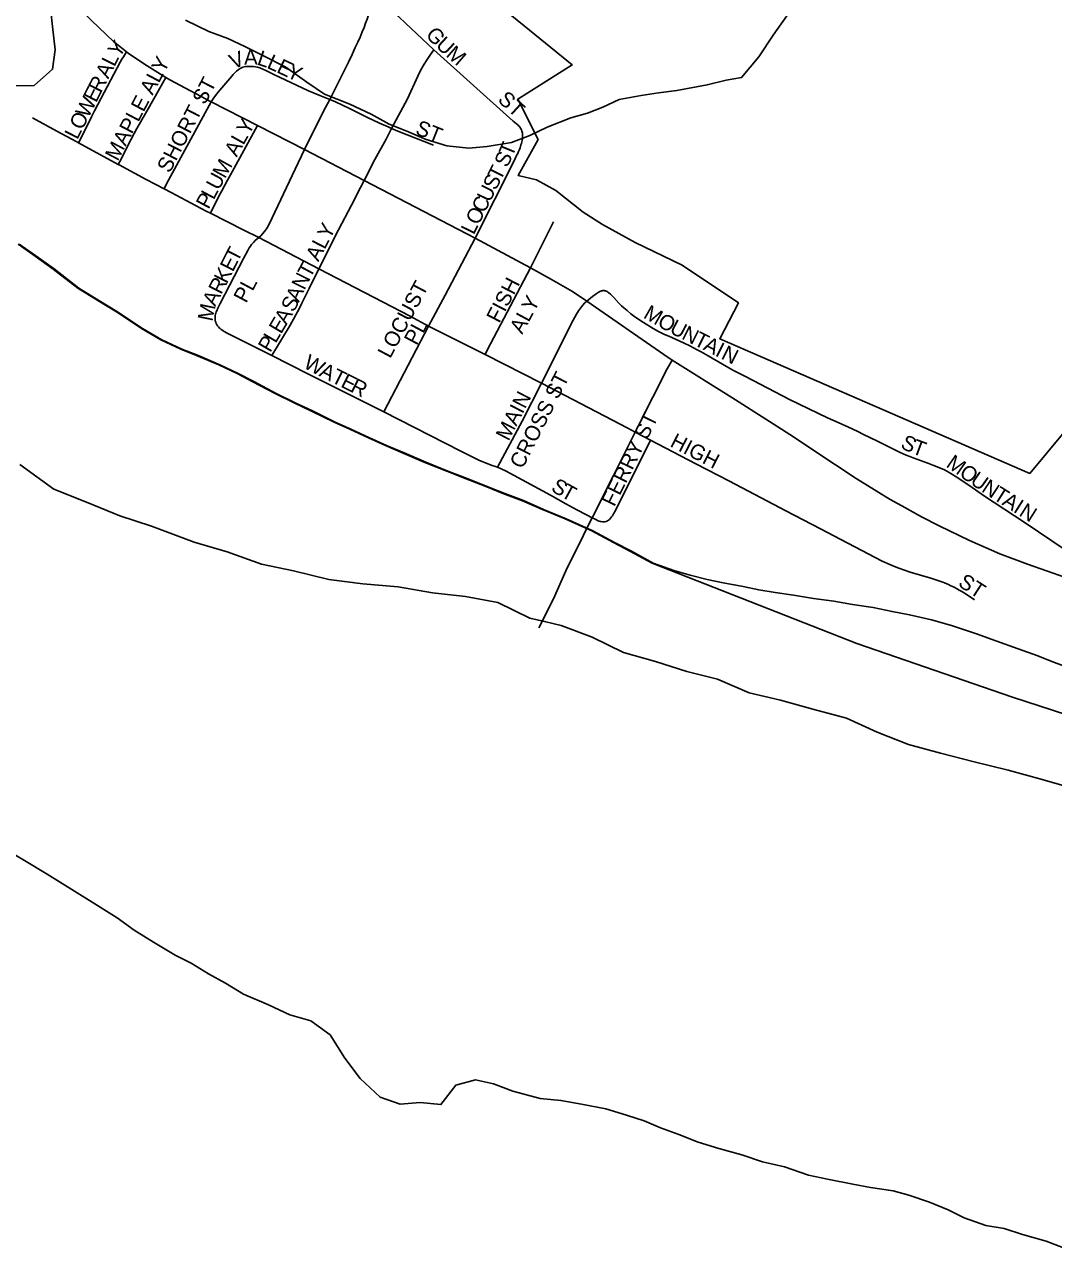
# Model space of a CAD drawing. Extents: x 1451455 to 1749751, y 218250 to 574981.
# Drawn here: x 1607283 to 1610664, y 237680 to 241704 of the extents above; entities that cross this region are included whole.
import ezdxf

# ---------------------------------------------------------------- set-up
doc = ezdxf.new("R2010")
doc.units = 0
for name, color, linetype in [('GM_X_City_Street', 7, 'Continuous'), ('GM_X_City_Street_Text', 7, 'Continuous'), ('GM_X_Corporation', 7, 'Continuous'), ('GM_X_County', 7, 'Continuous'), ('GM_X_Major_River', 7, 'Continuous'), ('GM_X_Minor_River', 7, 'Continuous'), ('GM_X_State_Route', 7, 'Continuous'), ('GM_X_Township', 7, 'Continuous'), ('GM_X_US_Route', 7, 'Continuous')]:
    doc.layers.add(name, color=color, linetype=linetype)

msp = doc.modelspace()

# ---------------------------------------------------------------- linework, layer by layer
at = {"layer": 'GM_X_City_Street'}
for points in [[(1608429.3, 241787.9), (1608449.2, 241777.7), (1608463.9, 241769.2), (1608472.3, 241763.6), (1608479, 241758.7), (1608487.2, 241751.9), (1608515.3, 241727), (1608533.8, 241710.1), (1608628.5, 241621.2)], [(1607460.8, 241315.5), (1607465.7, 241325.6), (1607503.3, 241401.1), (1607513.4, 241420.6), (1607556, 241501.1), (1607597.7, 241580.2), (1607603.4, 241590.2), (1607608.2, 241598.1), (1607611.9, 241603.8), (1607618.9, 241614.4)], [(1608489.5, 241362.4), (1608541.2, 241460.3), (1608575.4, 241534.4), (1608585.8, 241555.6), (1608596.9, 241574.4), (1608606.3, 241589.6), (1608617.5, 241605.8), (1608628.5, 241621.2)], [(1608628.5, 241621.2), (1608889.2, 241387), (1608904.8, 241373.5), (1608907.7, 241370.5), (1608909.4, 241368.6), (1608910.8, 241366.9), (1608912.7, 241364.2), (1608914.4, 241361.6), (1608915.8, 241358.7), (1608917.7, 241354), (1608918.7, 241350.7), (1608919.4, 241347.3), (1608919.8, 241343.6)], [(1607896.5, 241449.8), (1607905.5, 241463), (1607914.5, 241475.1), (1607925.3, 241488), (1607957.9, 241526.6), (1607964.1, 241534), (1607969.1, 241539.6), (1607974.2, 241545.2), (1607980.1, 241551), (1607985.2, 241555.4), (1607991.6, 241559.9), (1607995.9, 241562.1), (1608000.2, 241563.6), (1608004.6, 241564.9), (1608009.6, 241565.9), (1608015.4, 241566.4), (1608021.3, 241566.6), (1608028.4, 241566.4), (1608035.4, 241566), (1608042.4, 241565), (1608048.3, 241563.8), (1608056.1, 241561.5), (1608065.9, 241557.7), (1608076.2, 241552.9), (1608102.4, 241540.4), (1608216.3, 241485.9), (1608253.9, 241470.9), (1608285.9, 241458.1)], [(1607591.5, 241244.4), (1607596.6, 241254.4), (1607632.8, 241325.6), (1607643.5, 241346), (1607652.6, 241362.7), (1607681.1, 241411.8), (1607712.7, 241468), (1607737.5, 241512.2), (1607747.8, 241530.5)], [(1607741.7, 241164.7), (1607750.3, 241180.7), (1607896.5, 241449.8)], [(1608285.9, 241458.1), (1608305.5, 241450.3), (1608350.7, 241428.7), (1608410.2, 241398.9), (1608449.7, 241380.3), (1608478, 241367.5), (1608489.5, 241362.4)], [(1607309.3, 241397.4), (1607389.5, 241353.6)], [(1607893.9, 241084.5), (1607922.2, 241139.9), (1607931.6, 241157.9), (1607950.1, 241192.6), (1607965.6, 241220.5), (1608048.7, 241371.9)], [(1608399.6, 241191.8), (1608434.8, 241260.7), (1608471.1, 241328), (1608489.5, 241362.4)], [(1608489.5, 241362.4), (1608509.7, 241353.9), (1608626.8, 241307.7)], [(1607389.5, 241353.6), (1607453.1, 241319.7), (1607460.8, 241315.5)], [(1607460.8, 241315.5), (1607591.5, 241244.4)], [(1608763.7, 241002.2), (1608891.9, 241256), (1608896.8, 241266.4), (1608900.2, 241273.5), (1608903.6, 241280.9), (1608906.2, 241286.7), (1608909.1, 241293.6), (1608911.3, 241299.5), (1608914.5, 241308.7), (1608915.9, 241313.6), (1608917.2, 241318.6), (1608918.2, 241323.6), (1608918.9, 241327.7), (1608919.6, 241333.4), (1608919.7, 241336.2), (1608919.8, 241340.1), (1608919.8, 241343.6)], [(1608052.7, 241004.5), (1608059.2, 241010.4), (1608065.7, 241017), (1608071.8, 241023.9), (1608078.5, 241032.9), (1608081.9, 241038.1), (1608087.4, 241048.5), (1608172.7, 241229.1), (1608203.2, 241293.5)], [(1607591.5, 241244.4), (1607593.8, 241243.2), (1607683.3, 241195.3), (1607741.7, 241164.7)], [(1607741.7, 241164.7), (1607764.6, 241152.7), (1607880.3, 241091.2), (1607893.9, 241084.5)], [(1608250.5, 240901.9), (1608315.3, 241029.2), (1608357.9, 241110.3), (1608387.7, 241168.4), (1608399.6, 241191.8)], [(1607893.9, 241084.5), (1608004.4, 241028.7), (1608052.7, 241004.5)], [(1608946.2, 240905.2), (1609021.1, 241056.3)], [(1607910.1, 240731.3), (1607909.7, 240735.3), (1607909.5, 240739.7), (1607909.6, 240741.6), (1607909.9, 240746.2), (1607910.2, 240748.3), (1607911, 240752.8), (1607911.7, 240755.6), (1607913.4, 240760.8), (1607914.8, 240764.1), (1607918.8, 240772.6), (1607926.3, 240787.7), (1608002.8, 240935.4), (1608017.1, 240962.3), (1608021.5, 240970.1), (1608025.3, 240975.9), (1608029.3, 240981.2), (1608035.8, 240988.6), (1608041.6, 240994.2), (1608052.7, 241004.5)], [(1608052.7, 241004.5), (1608250.5, 240901.9)], [(1608611, 240713.7), (1608665.3, 240814.8), (1608763.7, 241002.2)], [(1608095.9, 240616.5), (1608155.7, 240716.8), (1608166.8, 240735.8), (1608174.8, 240750.1), (1608180.2, 240760.3), (1608185.2, 240770.3), (1608194.2, 240788.6), (1608218.2, 240837.3), (1608250.5, 240901.9)], [(1608250.5, 240901.9), (1608550.1, 240746.3), (1608611, 240713.7)], [(1608796.5, 240620.1), (1608803.8, 240634), (1608946.2, 240905.2)], [(1608982.3, 240526.1), (1609085.9, 240732.8), (1609096.7, 240752.9), (1609103.5, 240764), (1609116.3, 240781.4), (1609123, 240788.5), (1609130.5, 240795.4)], [(1609130.5, 240795.4), (1609149.3, 240811.1), (1609161.2, 240820), (1609167.7, 240824), (1609173.2, 240826.9), (1609176.9, 240828.4), (1609178.6, 240829), (1609181.2, 240829.6), (1609182.9, 240829.9), (1609185.1, 240830.2), (1609186.1, 240830.2), (1609188.2, 240830), (1609190.2, 240829.8), (1609192.5, 240829.2), (1609194.7, 240828.4), (1609197.6, 240826.8), (1609200.1, 240825.3), (1609202.9, 240823.2), (1609208.7, 240818.1), (1609219.6, 240807.1), (1609235.7, 240789.3), (1609244.7, 240780.4), (1609252.1, 240773.5), (1609263.1, 240764.3), (1609275.7, 240754.2), (1609288.2, 240744.2), (1609316.5, 240724.9), (1609348.3, 240706.1), (1609366, 240696.2), (1609379.1, 240689.4), (1609386, 240686.1), (1609399.7, 240680), (1609409.7, 240675.8), (1609426.4, 240668.4), (1609434.4, 240664.6), (1609450.9, 240657), (1609469, 240648.5), (1609493.7, 240635.8), (1609507, 240628.4), (1609529.1, 240615.3), (1609610.2, 240568.8), (1609652.5, 240547.6), (1609796.8, 240472.8), (1609922, 240412.1), (1609956.8, 240397.1), (1610002.5, 240375.8), (1610020.7, 240366.9), (1610039.3, 240357.4), (1610083.1, 240336.3), (1610134.4, 240311.3), (1610160.1, 240298.6), (1610180.1, 240289.7), (1610191.8, 240284.9), (1610203, 240280.5), (1610250.9, 240263.5)], [(1607910.1, 240731.3), (1607911.4, 240726.4), (1607912.8, 240722.4), (1607914.1, 240719.7), (1607916, 240716.4), (1607917.2, 240714.7), (1607919.5, 240711.7), (1607920.4, 240710.6), (1607924, 240706.9), (1607925.9, 240705.2), (1607929.3, 240702.5), (1607931.1, 240701.2), (1607935.5, 240698.2), (1607939.2, 240695.8), (1607948.6, 240690.6), (1608095.9, 240616.5)], [(1608463.7, 240432.3), (1608543.9, 240585.5), (1608611, 240713.7)], [(1608611, 240713.7), (1608796.5, 240620.1)], [(1608095.9, 240616.5), (1608214.5, 240556.9), (1608463.7, 240432.3)], [(1608796.5, 240620.1), (1608982.3, 240526.1)], [(1608837.2, 240250.5), (1608918.1, 240401.5), (1608982.3, 240526.1)], [(1608982.3, 240526.1), (1609265.3, 240378), (1609289.9, 240365.1), (1609340.1, 240338.7)], [(1608463.7, 240432.3), (1608717.1, 240302.3), (1608778.5, 240272.1), (1608797.8, 240263.8), (1608816.5, 240256.7), (1608837.2, 240250.5)], [(1609194.2, 240071.4), (1609198.8, 240073.3), (1609202.3, 240075.5), (1609205.5, 240078.2), (1609208.8, 240082.1), (1609212.2, 240086.6), (1609214.8, 240090.5), (1609218.8, 240097.2), (1609223.8, 240106.1), (1609266.3, 240192.1), (1609330.9, 240320.5), (1609340.1, 240338.7)], [(1609340.1, 240338.7), (1609488.9, 240261.4), (1609599.7, 240204), (1609784.9, 240106.9), (1609898.8, 240047.5), (1610101.5, 239941.7), (1610126.2, 239930.3), (1610141.5, 239923.9), (1610156, 239918.3), (1610174.1, 239911.9), (1610193.6, 239905.4), (1610260.8, 239885.4), (1610277.6, 239880), (1610290.5, 239875.5), (1610300.1, 239872), (1610305.9, 239869.8), (1610314.1, 239866.4), (1610319, 239864.3), (1610326.9, 239860.8), (1610335.2, 239856.8), (1610345.7, 239851.2), (1610354.4, 239846.5), (1610362.6, 239841.6), (1610376.8, 239832.9), (1610404.2, 239814.6)], [(1608837.2, 240250.5), (1608863.1, 240237.6), (1608932.8, 240201), (1609010.9, 240158.2), (1609062.2, 240129.9), (1609098.5, 240110.2), (1609129.9, 240093.5), (1609148.4, 240084), (1609157.8, 240079.2), (1609168.3, 240074.2), (1609171.7, 240073), (1609175.1, 240071.9), (1609178.4, 240071.1), (1609182, 240070.6), (1609185.9, 240070.4), (1609189.8, 240070.7), (1609194.2, 240071.4)], [(1610250.9, 240263.5), (1610268.1, 240257), (1610292.5, 240247), (1610306, 240240.8), (1610321.6, 240232.4), (1610340.5, 240220.9), (1610385.4, 240190.6), (1610436.9, 240154.9), (1610567.5, 240069.1), (1610706.2, 239976.3)]]:
    msp.add_lwpolyline(points, dxfattribs=at)
at = {"layer": 'GM_X_Corporation'}
for points in [[(1608422.8, 242108.6), (1609082.9, 241571.6), (1608903.8, 241459), (1608970.7, 241325.9), (1608905.6, 241208.1), (1608965.6, 241193.5), (1609029.3, 241158.8), (1609118.8, 241087.7), (1609182.5, 241047), (1609290.1, 240987.7), (1609443.6, 240914), (1609628.7, 240789.9), (1609567.6, 240672.1), (1610585.9, 240229.7), (1610758.7, 240435.7)], [(1610795.8, 239408.3), (1610529.5, 239494.8), (1610018, 239670.8), (1609345.7, 239934.6), (1609274.1, 239973.5), (1609218.4, 240002.2), (1609146.8, 240041), (1609059.2, 240080.1), (1608985.5, 240111), (1608919.8, 240139.8), (1608858, 240162.6), (1608802.2, 240185.3), (1608734.5, 240212.1), (1608670.7, 240236.9), (1608599, 240265.7), (1608527.3, 240296.6), (1608469.6, 240321.3), (1608413.8, 240346), (1608352.1, 240374.8), (1608300.3, 240397.4), (1608226.7, 240434.3), (1608168.9, 240461), (1608107.3, 240491.8), (1608033.6, 240530.7), (1607981.9, 240557.3), (1607922.2, 240586.1), (1607848.5, 240617), (1607796.7, 240637.6), (1607731, 240668.4), (1607667.4, 240705.2), (1607586, 240760.3), (1607524.3, 240797.1), (1607458.7, 240837.9), (1607377.4, 240901), (1607317.8, 240943.7), (1607262.2, 240982.4)]]:
    msp.add_lwpolyline(points, dxfattribs=at)
at = {"layer": 'GM_X_County'}
msp.add_lwpolyline([(1607268.3, 240259), (1607379.9, 240177.6), (1607492.1, 240132.7), (1607596.6, 240090.4), (1607700.9, 240056.2), (1607841, 240004), (1607949.1, 239972), (1608061.8, 239931.6), (1608166.8, 239909.4), (1608283.5, 239881.1), (1608395, 239866.9), (1608511.3, 239856.9), (1608624.1, 239837), (1608732, 239825), (1608838.5, 239805.6), (1608944, 239753.7), (1608991.3, 239742.6), (1609047, 239729.5), (1609148.8, 239692.2), (1609251.4, 239641.8), (1609356.8, 239611.3), (1609459.1, 239579.2), (1609560.1, 239553.4), (1609664.2, 239509.2), (1609767.4, 239484.9), (1609873, 239454.9), (1609983.5, 239425.3), (1610084.4, 239379.7), (1610187.9, 239339), (1610293, 239310.6), (1610403.1, 239282.6), (1610515, 239254.6), (1610626.6, 239224.6), (1610745, 239190.4)], dxfattribs=at)
at = {"layer": 'GM_X_Major_River'}
for points in [[(1607203.9, 241029.7), (1607195.2, 241154.1), (1607206, 241220.2), (1607194.6, 241282.5), (1607161.4, 241353), (1607137.9, 241405.4), (1607136.6, 241471.6), (1607197, 241505), (1607249, 241502.4), (1607315, 241503.7), (1607375.6, 241557.1), (1607384.3, 241621.2), (1607375.1, 241697.5), (1607369.7, 241747.6), (1607352.4, 241816), (1607309.1, 241880.7), (1607275, 241896.1)], [(1610733.7, 239584.7), (1610663.9, 239609.5), (1610612.1, 239630.2), (1610548.3, 239652.9), (1610474.6, 239679.8), (1610410.8, 239702.6), (1610329.1, 239729.6), (1610263.2, 239748.4), (1610191.4, 239765.2), (1610133.5, 239775.9), (1610071.6, 239788.6), (1610003.7, 239799.4), (1609941.8, 239810.1), (1609875.9, 239818.9), (1609810, 239829.6), (1609750, 239838.3), (1609696.1, 239847), (1609644.2, 239857.6), (1609578.3, 239870.3), (1609526.4, 239880.9), (1609470.5, 239895.6), (1609416.7, 239910.2), (1609348.9, 239935), (1609277.3, 239973.9), (1609221.6, 240002.6), (1609150, 240041.5), (1609062.4, 240080.6), (1608988.7, 240111.5), (1608923, 240140.3), (1608861.2, 240163.1), (1608805.4, 240185.7), (1608737.7, 240212.6), (1608673.9, 240237.3), (1608602.2, 240266.2), (1608530.5, 240297.1), (1608472.8, 240321.8), (1608417, 240346.5), (1608355.3, 240375.2), (1608303.5, 240397.9), (1608229.9, 240434.8), (1608172.2, 240461.5), (1608110.5, 240492.3), (1608036.9, 240531.2), (1607985.1, 240557.8), (1607925.4, 240586.6), (1607851.7, 240617.5), (1607799.9, 240638.1), (1607734.2, 240668.9), (1607670.6, 240705.7), (1607589.2, 240760.8), (1607527.5, 240797.5), (1607462, 240838.4), (1607380.6, 240901.4), (1607321, 240944.2), (1607265.4, 240982.9)], [(1607196.3, 239008.8), (1607283.7, 238957.7), (1607357.3, 238912.8), (1607496.4, 238827), (1607587.8, 238769.8), (1607643.4, 238729.1), (1607707, 238690.3), (1607778.6, 238647.4), (1607830.3, 238620.8), (1607888, 238586), (1607943.7, 238555.3), (1608003.3, 238518.6), (1608084.9, 238483.6), (1608154.6, 238450.7), (1608224.4, 238431.9), (1608288, 238385.1), (1608335.2, 238308.4), (1608386.5, 238241.6), (1608451.8, 238180.7), (1608517.6, 238157.9), (1608583.7, 238163.2), (1608651.6, 238156.4), (1608700.3, 238220), (1608764.5, 238237.4), (1608824.4, 238224.7), (1608888.2, 238199.9), (1608978, 238176.8), (1609045.9, 238170.1), (1609113.8, 238157.3), (1609193.7, 238142.4), (1609261.5, 238121.5), (1609319.3, 238102.9), (1609373.1, 238080.2), (1609432.9, 238057.5), (1609496.6, 238032.7), (1609564.4, 238011.9), (1609640.2, 237991), (1609708, 237968.2), (1609779.8, 237951.3), (1609859.6, 237924.4), (1609921.5, 237911.6), (1610005.3, 237894.7), (1610063.2, 237884), (1610137.1, 237873.1), (1610189, 237858.5), (1610256.8, 237835.7), (1610318.5, 237811), (1610370.3, 237784.3), (1610442, 237759.4), (1610501.9, 237748.8), (1610561.7, 237730), (1610639.5, 237707.1), (1610711.3, 237680.2)]]:
    msp.add_lwpolyline(points, dxfattribs=at)
at = {"layer": 'GM_X_Minor_River'}
msp.add_lwpolyline([(1607811.9, 241718.9), (1607889.4, 241681.6), (1607951.2, 241658.7), (1608006.8, 241631.8), (1608068.4, 241600.9), (1608142, 241563.7), (1608211.3, 241514.6), (1608268.8, 241475.6), (1608352.4, 241442.3), (1608422, 241409.2), (1608481.6, 241376.3), (1608539.3, 241353.4), (1608603, 241326.4), (1608670.8, 241305.4), (1608742.7, 241298.3), (1608802.9, 241303.5), (1608883.1, 241316.4), (1608943.5, 241339.6), (1609000, 241366.9), (1609078.5, 241397.8), (1609132.8, 241413.1), (1609183.1, 241432.4), (1609237.5, 241457.7), (1609309.8, 241470.7), (1609366, 241479.9), (1609426.2, 241487.1), (1609526.5, 241505.7), (1609588.8, 241520.9), (1609639, 241530.2), (1609696, 241597.5), (1609743.1, 241669.1), (1609788.1, 241732.6)], dxfattribs=at)
at = {"layer": 'GM_X_State_Route'}
for points in [[(1608203.2, 241293.5), (1608265, 241416.9), (1608285.9, 241458.1), (1608335.4, 241556.3), (1608347.6, 241580.6), (1608359.3, 241605.4), (1608370.2, 241628.8), (1608378.4, 241646.6), (1608385.8, 241663.1), (1608392.7, 241679.6), (1608398.8, 241694.8), (1608404, 241708.6), (1608408.8, 241722.1), (1608413.6, 241736.4), (1608417.5, 241748.6), (1608421, 241760), (1608424.9, 241772.5), (1608429.3, 241787.9)], [(1609137.8, 240063), (1609148.4, 240084), (1609218.3, 240223), (1609289.9, 240365.1), (1609300.9, 240387), (1609394.7, 240572.6), (1609411.4, 240601.2)], [(1608973.1, 239721.8), (1609020.9, 239817.4), (1609061.9, 239909.1), (1609119.8, 240026.7), (1609137.8, 240063)]]:
    msp.add_lwpolyline(points, dxfattribs=at)
at = {"layer": 'GM_X_Township'}
msp.add_lwpolyline([(1610745, 239190.4), (1610626.6, 239224.6), (1610515, 239254.6), (1610403.1, 239282.6), (1610293, 239310.6), (1610187.9, 239339), (1610084.4, 239379.7), (1609983.5, 239425.3), (1609873, 239454.9), (1609767.4, 239484.9), (1609664.2, 239509.2), (1609560.1, 239553.4), (1609459.1, 239579.2), (1609356.8, 239611.3), (1609251.4, 239641.8), (1609148.8, 239692.2), (1609047, 239729.5), (1608991.3, 239742.6), (1608944, 239753.7), (1608838.5, 239805.6), (1608732, 239825), (1608624.1, 239837), (1608511.3, 239856.9), (1608395, 239866.9), (1608283.5, 239881.1), (1608166.8, 239909.4), (1608061.8, 239931.6), (1607949.1, 239972), (1607841, 240004), (1607700.9, 240056.2), (1607596.6, 240090.4), (1607492.1, 240132.7), (1607379.9, 240177.6), (1607268.3, 240259)], dxfattribs=at)
at = {"layer": 'GM_X_US_Route'}
for points in [[(1606498.4, 243395.5), (1606615.8, 243185.6), (1606646.6, 243132.1), (1606652.4, 243122), (1606686.9, 243061.5), (1606688.4, 243058.9), (1606858.3, 242757.8), (1607080.4, 242361.3), (1607241, 242080.1), (1607314.7, 241951.8), (1607353.8, 241891.9), (1607399.4, 241828.7), (1607443, 241779.8), (1607503.1, 241717.1), (1607575.7, 241648.7), (1607590.6, 241636.8)], [(1607590.6, 241636.8), (1607618.9, 241614.4), (1607623.9, 241610.5), (1607677.2, 241573.7), (1607747.8, 241530.5), (1607760.5, 241522.7), (1607896.5, 241449.8), (1608048.7, 241371.9), (1608102.5, 241344.7), (1608203.2, 241293.5)], [(1608203.2, 241293.5), (1608399.6, 241191.8), (1608763.7, 241002.2), (1608946.2, 240905.2), (1609014.2, 240866.9), (1609084.1, 240826.8), (1609130.5, 240795.4), (1609383.9, 240619.9), (1609411.4, 240601.2)], [(1609411.4, 240601.2), (1609606.9, 240479), (1609731, 240399.9), (1609797.3, 240357.5), (1609947.4, 240257.9), (1610015.7, 240212.8), (1610127.2, 240144), (1610165.4, 240122.8)], [(1610165.4, 240122.8), (1610230, 240087), (1610288.2, 240057.6), (1610388.4, 240009.2), (1610487.3, 239965.9), (1610578.3, 239931.9), (1610703.2, 239887.6), (1610858.8, 239837.1), (1610898.1, 239824.9), (1611171.2, 239740.8), (1611353.8, 239684.1), (1611438.8, 239659.4), (1611596.3, 239613.7)]]:
    msp.add_lwpolyline(points, dxfattribs=at)

# ---------------------------------------------------------------- texts
at = {"layer": 'GM_X_City_Street_Text'}
for s, rotation, p in [('G', 312.4413, (1608598.6, 241668.4)), ('Y', 53.4006, (1607593.3, 241592.1)), ('U', 317.2788, (1608631.5, 241632.7)), ('MAPLE ALY', 62.1717, (1607589.3, 241252.9)), ('V', 22.155, (1607968.8, 241556)), ('A', 1.1694, (1608004.8, 241571.7)), ('L', 341.5424, (1608044.4, 241573.2)), ('L', 335.9623, (1608076.6, 241562.5)), ('M', 318.9796, (1608665.1, 241601.7)), ('A', 63.0286, (1607558.5, 241523.4)), ('L', 63.0317, (1607578.5, 241562.6)), ('E', 334.7731, (1608108.4, 241548.3)), ('Y', 334.7695, (1608140.3, 241533.3)), ('R', 63.0276, (1607534.5, 241476.4)), ('SHORT ST', 62.6511, (1607760.3, 241213.4)), ('E', 63.0058, (1607518.5, 241445)), ('ST', 317.4929, (1608835.4, 241453.6)), ('W', 63.0214, (1607492.6, 241394)), ('O', 63.0248, (1607472.6, 241354.8)), ('ALY', 60.7514, (1607980.4, 241266.5)), ('L', 63.0058, (1607456.6, 241323.4)), ('ST', 338.1977, (1608564.1, 241345.4)), ('T', 67.6138, (1608886.1, 241266.6)), ('S', 63.5242, (1608868.8, 241231.5)), ('M', 61.0436, (1607941.8, 241195.4)), ('T', 63.522, (1608847.2, 241188.2)), ('U', 61.8452, (1607921.1, 241156.8)), ('S', 63.5328, (1608831.6, 241156.7)), ('L', 61.8581, (1607904.5, 241125.7)), ('U', 63.518, (1608811.9, 241117.3)), ('P', 61.8343, (1607887.9, 241094.7)), ('C', 63.5293, (1608794.3, 241081.8)), ('O', 63.518, (1608774.7, 241042.4)), ('ALY', 62.5248, (1608248.7, 240923)), ('L', 63.522, (1608759, 241010.9)), ('T', 62.9447, (1607983.5, 240920.4)), ('E', 62.9126, (1607967.4, 240889)), ('T', 61.77, (1608222.2, 240868.2)), ('K', 62.9266, (1607947.4, 240849.9)), ('N', 63.7367, (1608203, 240829.2)), ('FISH', 62.5925, (1608842.6, 240720.6)), ('R', 62.9448, (1607929.4, 240814.6)), ('PL', 61.929, (1608011.4, 240786.3)), ('A', 65.3151, (1608184.7, 240789.5)), ('LOCUST', 61.9893, (1608484.7, 240604.5)), ('A', 63.6866, (1607909.9, 240775.3)), ('S', 63.0112, (1608167.8, 240756.2)), ('ALY', 61.6994, (1608918.4, 240684.4)), ('M', 78.2985, (1607900.3, 240726.8)), ('A', 59.5995, (1608144, 240715.4)), ('M', 330.2949, (1609313.3, 240742.1)), ('O', 330.5271, (1609359.3, 240715.8)), ('E', 59.5791, (1608126.2, 240685)), ('PL', 61.929, (1608571.7, 240647.3)), ('U', 332.5894, (1609399.4, 240693.2)), ('N', 333.4028, (1609439.1, 240672.6)), ('P', 59.5791, (1608090.5, 240624.3)), ('L', 59.6014, (1608108.3, 240654.6)), ('T', 333.4346, (1609478.5, 240652.9)), ('A', 333.435, (1609510, 240637.1)), ('I', 333.4154, (1609549.3, 240617.5)), ('N', 333.4361, (1609569, 240607.6)), ('W', 331.6187, (1608196.4, 240578.8)), ('A', 333.3348, (1608248.1, 240550.9)), ('T', 333.4352, (1608287.5, 240531.1)), ('E', 333.4411, (1608319, 240515.4)), ('CROSS ST', 63.0349, (1608919.3, 240241.5)), ('R', 333.4322, (1608350.5, 240499.6)), ('MAIN', 62.7418, (1608873.4, 240333.4)), ('FERRY ST', 63.8391, (1609220.9, 240117.6)), ('HIGH', 332.698, (1609401, 240319.8)), ('S', 332.9798, (1610158.2, 240315.2)), ('T', 339.6164, (1610195.4, 240296.7)), ('M', 325.0356, (1610308, 240253.5)), ('O', 325.0322, (1610351.2, 240223.2)), ('U', 325.0481, (1610387.3, 240198)), ('S', 328.8143, (1609010, 240174.2)), ('T', 331.3836, (1609042.2, 240154.8)), ('N', 326.4995, (1610424.5, 240172)), ('T', 327.6633, (1610462.1, 240147.1)), ('A', 327.7134, (1610491.9, 240128.3)), ('I', 327.735, (1610529.1, 240104.8)), ('N', 327.7212, (1610547.7, 240093)), ('ST', 327.2691, (1610347.4, 239861.9))]:
    msp.add_text(s, height=50, rotation=rotation, dxfattribs=at).set_placement(p)

doc.saveas('drawing.dxf')
